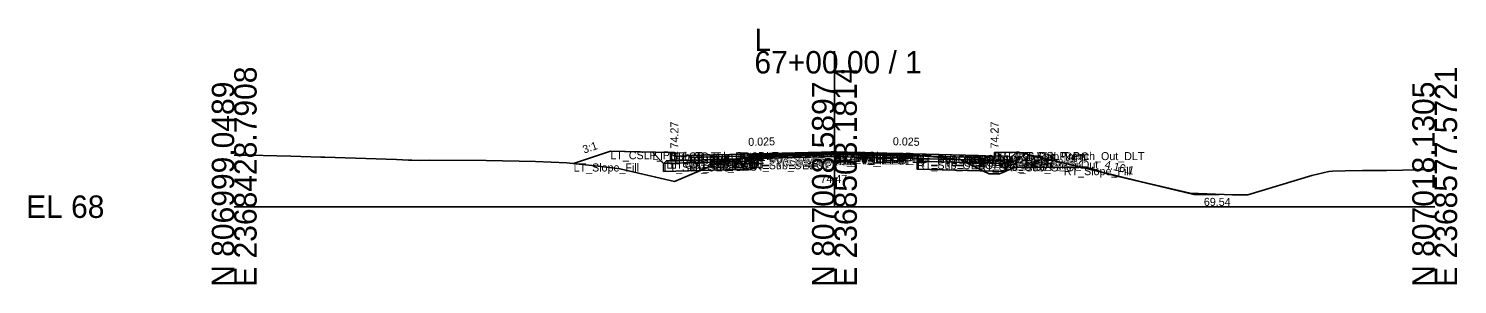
# Model space of a CAD drawing. Extents: x -26 to 8153, y -10 to 9520.
# Drawn here: x 5974.3 to 6152.8, y 7490.3 to 7522.2 of the extents above; entities that cross this region are included whole.
import ezdxf

# ---------------------------------------------------------------- set-up
doc = ezdxf.new("R2010")
doc.units = 0
for name, color, linetype in [('Exist CMT Pavement', 7, 'Continuous'), ('Exist Cross Section Cell', 7, 'Continuous'), ('Exist XS Center Line Elevation Label', 7, 'Continuous'), ('Exist XS Ground Line', 7, 'Continuous'), ('Prop CMT Conc Surface', 7, 'Continuous'), ('Prop CMT Concrete Structures', 7, 'Continuous'), ('Prop CMT Ditch DDE', 7, 'Continuous'), ('Prop CMT Pvmt Course 1', 7, 'Continuous'), ('Prop CMT Pvmt Course 1 CG', 7, 'Continuous'), ('Prop CMT Pvmt Course 1 Wedge', 7, 'Continuous'), ('Prop CMT Pvmt Course 2', 7, 'Continuous'), ('Prop CMT Pvmt Course 2 Wedge', 7, 'Continuous'), ('Prop CMT Pvmt Course 3', 7, 'Continuous'), ('Prop CMT Pvmt Course 3 Wedge', 7, 'Continuous'), ('Prop CMT Pvmt Surface', 7, 'Continuous'), ('Prop CMT Pvmt Wedge Surface 1', 7, 'Continuous'), ('Prop CMT Pvmt Wedge Surface 2', 7, 'Continuous'), ('Prop CMT Pvmt Wedge Surface 3', 7, 'Continuous'), ('Prop CMT Shallow Undercut', 7, 'Continuous'), ('Prop CMT Shallow Undercut Boundary', 7, 'Continuous'), ('Prop CMT Slope Grass', 7, 'Continuous'), ('Prop CMT Subgrade Earthwork', 7, 'Continuous'), ('Prop XS Earthwork Shape', 7, 'Continuous'), ('Prop XS Hydro Elevations', 7, 'Continuous'), ('Prop XS SE Text', 7, 'Continuous'), ('Prop XS Side Slope Text', 7, 'Continuous'), ('Prop XS Subgrade Earthwork', 7, 'Continuous'), ('Scratch_Level_2', 7, 'Continuous'), ('Scratch_Level_6', 7, 'Continuous')]:
    doc.layers.add(name, color=color, linetype=linetype)

msp = doc.modelspace()

# ---------------------------------------------------------------- linework, layer by layer
at = {"layer": 'Exist CMT Pavement'}
for p, q in [((6064.49, 7506.17), (6070.63, 7506.34)), ((6070.63, 7506.34), (6074.8, 7506.47)), ((6074.8, 7506.47), (6077.93, 7506.44)), ((6077.93, 7506.44), (6085.34, 7506.38))]:
    msp.add_line(p, q, dxfattribs=at)
at = {"layer": 'Exist Cross Section Cell'}
for p, q in [((6075, 7500), (6075, 7519.42)), ((6000, 7500), (6075, 7500)), ((6075, 7500), (6150, 7500))]:
    msp.add_line(p, q, dxfattribs=at)
at = {"layer": 'Exist XS Ground Line'}
for p, q in [((6000, 7506.43), (6001.22, 7506.44)), ((6001.22, 7506.44), (6001.89, 7506.42)), ((6001.89, 7506.42), (6007.08, 7506.29)), ((6007.08, 7506.29), (6010.83, 7506.19)), ((6010.83, 7506.19), (6011.31, 7506.19)), ((6011.31, 7506.19), (6020.29, 7505.89)), ((6020.29, 7505.89), (6021.77, 7505.81)), ((6021.77, 7505.81), (6022.18, 7505.82)), ((6022.18, 7505.82), (6023.18, 7505.78)), ((6023.18, 7505.78), (6024.41, 7505.8)), ((6024.41, 7505.8), (6031.47, 7505.77)), ((6031.47, 7505.77), (6037.63, 7505.63)), ((6037.63, 7505.63), (6041.55, 7505.49)), ((6055.82, 7503.47), (6060.95, 7505.68)), ((6060.95, 7505.68), (6061.46, 7505.74)), ((6061.46, 7505.74), (6064.49, 7506.17)), ((6064.49, 7506.17), (6070.63, 7506.34)), ((6070.63, 7506.34), (6074.8, 7506.47)), ((6074.8, 7506.47), (6077.93, 7506.44)), ((6077.93, 7506.44), (6085.34, 7506.38)), ((6085.34, 7506.38), (6087.86, 7506.19)), ((6087.86, 7506.19), (6090.7, 7505.87)), ((6090.7, 7505.87), (6091.42, 7505.51)), ((6041.55, 7505.49), (6045.87, 7505.01)), ((6045.87, 7505.01), (6048.2, 7504.74)), ((6048.2, 7504.74), (6052.68, 7503.68)), ((6091.42, 7505.51), (6094.34, 7504.09)), ((6094.34, 7504.09), (6095.62, 7504.08)), ((6095.62, 7504.08), (6096.88, 7504.63)), ((6096.88, 7504.63), (6097.59, 7504.89)), ((6097.59, 7504.89), (6105.43, 7504.94)), ((6105.43, 7504.94), (6106.45, 7504.92)), ((6106.45, 7504.92), (6109.06, 7504.08)), ((6109.06, 7504.08), (6119.45, 7501.7)), ((6126.65, 7501.49), (6134.66, 7503.9)), ((6134.66, 7503.9), (6136.77, 7504.41)), ((6136.77, 7504.41), (6137.21, 7504.45)), ((6137.21, 7504.45), (6138.8, 7504.49)), ((6138.8, 7504.49), (6141, 7504.51)), ((6141, 7504.51), (6142.46, 7504.5)), ((6142.46, 7504.5), (6143.98, 7504.52)), ((6143.98, 7504.52), (6150, 7504.65)), ((6052.68, 7503.68), (6055.03, 7503.14)), ((6055.03, 7503.14), (6055.82, 7503.47)), ((6119.45, 7501.7), (6124.72, 7501.47)), ((6124.72, 7501.47), (6126.65, 7501.49))]:
    msp.add_line(p, q, dxfattribs=at)
at = {"layer": 'Prop CMT Conc Surface'}
for points in [[(6055, 7506.27), (6055, 7506.77), (6054.5, 7506.77)], [(6057, 7506.4), (6055, 7506.27)], [(6093, 7506.4), (6095, 7506.27)], [(6095, 7506.27), (6095, 7506.77), (6095.5, 7506.77)]]:
    msp.add_lwpolyline(points, dxfattribs=at)
at = {"layer": 'Prop CMT Concrete Structures'}
for points in [[(6057, 7506.4), (6055, 7506.27), (6055, 7506.77), (6054.5, 7506.77)], [(6054.5, 7506.77), (6054.5, 7505.75), (6057, 7505.81)], [(6057, 7505.81), (6057, 7506.4)], [(6093, 7506.4), (6095, 7506.27), (6095, 7506.77), (6095.5, 7506.77)], [(6095.5, 7506.77), (6095.5, 7505.75), (6093, 7505.81)], [(6093, 7505.81), (6093, 7506.4)]]:
    msp.add_lwpolyline(points, dxfattribs=at)
at = {"layer": 'Prop CMT Ditch DDE'}
msp.add_line((6119.92, 7501.54), (6123.05, 7501.54), dxfattribs=at)
msp.add_lwpolyline([(6115.58, 7502.58), (6119.92, 7501.54)], dxfattribs=at)
at = {"layer": 'Prop CMT Pvmt Course 1'}
for points in [[(6075, 7506.85), (6057, 7506.4)], [(6057, 7506.4), (6057, 7506.15)], [(6057, 7506.15), (6064.49, 7506.34)], [(6064.49, 7506.46), (6075, 7506.72)], [(6064.49, 7506.34), (6064.49, 7506.46)], [(6075, 7506.6), (6075, 7506.85)], [(6075, 7506.85), (6093, 7506.4)], [(6075, 7506.6), (6075, 7506.85)], [(6075, 7506.72), (6075, 7506.6), (6075, 7506.6)], [(6085.34, 7506.46), (6075, 7506.72)], [(6075, 7506.72), (6075, 7506.6), (6075, 7506.6)], [(6085.34, 7506.34), (6085.34, 7506.46)], [(6093, 7506.15), (6085.34, 7506.34)], [(6093, 7506.4), (6093, 7506.15)]]:
    msp.add_lwpolyline(points, dxfattribs=at)
at = {"layer": 'Prop CMT Pvmt Course 1 CG'}
for points in [[(6057, 7505.81), (6054, 7505.74), (6053.66, 7505.4)], [(6057, 7505.49), (6057, 7505.81)], [(6093, 7505.81), (6096, 7505.74), (6096.34, 7505.4)], [(6093, 7505.49), (6093, 7505.81)], [(6053.66, 7505.4), (6057, 7505.49)], [(6096.34, 7505.4), (6093, 7505.49)]]:
    msp.add_lwpolyline(points, dxfattribs=at)
at = {"layer": 'Prop CMT Pvmt Course 1 Wedge'}
for points in [[(6075, 7506.72), (6064.49, 7506.46)], [(6075, 7506.72), (6085.34, 7506.46)]]:
    msp.add_lwpolyline(points, dxfattribs=at)
at = {"layer": 'Prop CMT Pvmt Course 2'}
for points in [[(6064.49, 7506.34), (6057, 7506.15)], [(6057, 7506.15), (6057, 7505.82)], [(6057, 7505.82), (6064.49, 7506.01)], [(6064.49, 7506.01), (6064.49, 7506.34)], [(6085.34, 7506.01), (6085.34, 7506.34)], [(6085.34, 7506.34), (6093, 7506.15)], [(6093, 7505.82), (6085.34, 7506.01)], [(6093, 7506.15), (6093, 7505.82)]]:
    msp.add_lwpolyline(points, dxfattribs=at)
at = {"layer": 'Prop CMT Pvmt Course 2 Wedge'}
for points in [[(6075, 7506.6), (6064.49, 7506.34)], [(6075, 7506.6), (6085.34, 7506.34)]]:
    msp.add_lwpolyline(points, dxfattribs=at)
at = {"layer": 'Prop CMT Pvmt Course 3'}
for points in [[(6064.49, 7506.01), (6057, 7505.82)], [(6057, 7505.82), (6057, 7505.49)], [(6057, 7505.49), (6064.49, 7505.67)], [(6064.49, 7505.67), (6064.49, 7506.01)], [(6085.34, 7506.01), (6093, 7505.82)], [(6085.34, 7505.68), (6085.34, 7506.01)], [(6093, 7505.49), (6085.34, 7505.68)], [(6093, 7505.82), (6093, 7505.49)]]:
    msp.add_lwpolyline(points, dxfattribs=at)
at = {"layer": 'Prop CMT Pvmt Course 3 Wedge'}
for points in [[(6075, 7506.27), (6064.49, 7506.01)], [(6075, 7506.27), (6085.34, 7506.01)]]:
    msp.add_lwpolyline(points, dxfattribs=at)
at = {"layer": 'Prop CMT Pvmt Surface'}
for points in [[(6075, 7506.85), (6057, 7506.4)], [(6075, 7506.85), (6093, 7506.4)]]:
    msp.add_lwpolyline(points, dxfattribs=at)
at = {"layer": 'Prop CMT Pvmt Wedge Surface 1'}
for points in [[(6057, 7506.15), (6057, 7506.4)], [(6064.49, 7506.34), (6057, 7506.15)], [(6075, 7506.72), (6064.49, 7506.46)], [(6064.49, 7506.46), (6064.49, 7506.34)], [(6075, 7506.72), (6085.34, 7506.46)], [(6085.34, 7506.46), (6085.34, 7506.34)], [(6085.34, 7506.34), (6093, 7506.15)], [(6093, 7506.15), (6093, 7506.4)]]:
    msp.add_lwpolyline(points, dxfattribs=at)
at = {"layer": 'Prop CMT Pvmt Wedge Surface 2'}
for points in [[(6075, 7506.6), (6057, 7506.15)], [(6057, 7506.15), (6057, 7506.4)], [(6075, 7506.6), (6093, 7506.15)], [(6093, 7506.15), (6093, 7506.4)]]:
    msp.add_lwpolyline(points, dxfattribs=at)
at = {"layer": 'Prop CMT Pvmt Wedge Surface 3'}
for points in [[(6057, 7505.82), (6057, 7506.4)], [(6075, 7506.27), (6057, 7505.82)], [(6075, 7506.27), (6093, 7505.82)], [(6093, 7505.82), (6093, 7506.4)]]:
    msp.add_lwpolyline(points, dxfattribs=at)
at = {"layer": 'Prop CMT Shallow Undercut'}
for points in [[(6060.71, 7505.58), (6064.49, 7505.67), (6064.49, 7504.67), (6058.25, 7504.52)], [(6085.34, 7505.68), (6085.34, 7504.68), (6093.55, 7504.47), (6091.42, 7505.51), (6091.38, 7505.53)]]:
    msp.add_lwpolyline(points, close=True, dxfattribs=at)
at = {"layer": 'Prop CMT Shallow Undercut Boundary'}
for p, q in [((6064.49, 7505.67), (6064.49, 7504.67)), ((6085.34, 7505.68), (6085.34, 7504.68)), ((6053.66, 7505.4), (6053.66, 7504.4)), ((6053.66, 7504.4), (6064.49, 7504.67)), ((6085.34, 7504.68), (6096.34, 7504.4)), ((6096.34, 7505.4), (6096.34, 7504.4))]:
    msp.add_line(p, q, dxfattribs=at)
at = {"layer": 'Prop CMT Slope Grass'}
for points in [[(6054.5, 7506.77), (6047, 7506.92), (6042.41, 7505.39)], [(6095.5, 7506.77), (6098, 7506.82), (6115.58, 7502.58)]]:
    msp.add_lwpolyline(points, dxfattribs=at)
at = {"layer": 'Prop CMT Subgrade Earthwork'}
for points in [[(6057, 7505.49), (6053.66, 7505.4), (6052.25, 7506.81)], [(6064.49, 7505.67), (6057, 7505.49)], [(6064.49, 7505.67), (6064.5, 7506.17)], [(6085.34, 7505.68), (6085.32, 7506.38)], [(6085.34, 7505.68), (6093, 7505.49)], [(6093, 7505.49), (6096.34, 7505.4), (6097.75, 7506.81)]]:
    msp.add_lwpolyline(points, dxfattribs=at)
at = {"layer": 'Prop XS Earthwork Shape'}
for p, q in [((6119.45, 7501.7), (6115.58, 7502.58)), ((6115.58, 7502.58), (6119.92, 7501.54)), ((6123.05, 7501.54), (6119.45, 7501.7)), ((6119.92, 7501.54), (6123.05, 7501.54))]:
    msp.add_line(p, q, dxfattribs=at)
for points in [[(6047, 7506.92), (6042.41, 7505.39), (6045.87, 7505.01), (6048.2, 7504.74), (6052.68, 7503.68), (6055.03, 7503.14), (6055.82, 7503.47), (6058.25, 7504.52), (6053.66, 7504.4), (6053.66, 7505.4), (6052.25, 7506.81)], [(6060.71, 7505.58), (6057, 7505.49), (6053.66, 7505.4), (6053.66, 7504.4), (6058.25, 7504.52)], [(6064.49, 7505.67), (6064.49, 7504.67), (6058.25, 7504.52), (6060.71, 7505.58)], [(6064.49, 7506.17), (6064.5, 7506.17), (6064.49, 7505.67), (6060.71, 7505.58), (6060.95, 7505.68), (6061.46, 7505.74)], [(6085.34, 7505.68), (6085.32, 7506.38), (6085.34, 7506.38), (6087.86, 7506.19), (6090.7, 7505.87), (6091.38, 7505.53)], [(6085.34, 7505.68), (6091.38, 7505.53), (6091.42, 7505.51), (6093.55, 7504.47), (6085.34, 7504.68)], [(6093, 7505.49), (6096.34, 7505.4), (6096.34, 7504.4), (6093.55, 7504.47), (6091.42, 7505.51), (6091.38, 7505.53)], [(6096.34, 7505.4), (6097.75, 7506.81), (6098, 7506.82), (6105.83, 7504.93), (6105.43, 7504.94), (6097.59, 7504.89), (6096.88, 7504.63), (6096.34, 7504.4)], [(6093.55, 7504.47), (6094.34, 7504.09), (6095.62, 7504.08), (6096.34, 7504.4)], [(6105.83, 7504.93), (6106.45, 7504.92), (6108.1, 7504.39)], [(6108.1, 7504.39), (6115.58, 7502.58), (6109.06, 7504.08)]]:
    msp.add_lwpolyline(points, close=True, dxfattribs=at)
at = {"layer": 'Prop XS Subgrade Earthwork'}
for p, q in [((6053.66, 7505.4), (6064.49, 7505.67)), ((6085.34, 7505.68), (6096.34, 7505.4))]:
    msp.add_line(p, q, dxfattribs=at)
at = {"layer": 'Scratch_Level_6'}
for points in [[(6060.71, 7505.58), (6064.49, 7505.67), (6064.49, 7504.67), (6058.25, 7504.52)], [(6085.34, 7505.68), (6085.34, 7504.68), (6093.55, 7504.47), (6091.42, 7505.51), (6091.38, 7505.53)]]:
    msp.add_lwpolyline(points, close=True, dxfattribs=at)

# ---------------------------------------------------------------- texts
at = {"layer": 'Exist Cross Section Cell'}
for s, p in [('L', (6065, 7519.42)), ('67+00.00 / 1', (6065, 7516.62)), ('EL 68', (5974, 7498.6))]:
    msp.add_text(s, height=2.8, dxfattribs=at).set_placement(p)
for s, p in [('E 2368428.7908', (6002.8, 7490)), ('E 2368503.1814', (6077.8, 7490)), ('E 2368577.5721', (6152.8, 7490)), ('N 806999.0489', (6000, 7490)), ('N 807008.5897', (6075, 7490)), ('N 807018.1305', (6150, 7490))]:
    msp.add_text(s, height=2.8, rotation=90, dxfattribs=at).set_placement(p)
at = {"layer": 'Exist XS Center Line Elevation Label'}
msp.add_text('74.47', height=1, dxfattribs=at).set_placement((6073.25, 7502.97))
at = {"layer": 'Prop XS Hydro Elevations'}
for p in [(6055.5, 7507.27), (6095.5, 7507.27)]:
    msp.add_text('74.27', height=1, rotation=90, dxfattribs=at).set_placement(p)
at = {"layer": 'Prop XS SE Text'}
for rotation, p in [(1.4321, (6064.24, 7507.58)), (358.5679, (6082.29, 7507.67))]:
    msp.add_text('0.025', height=1, rotation=rotation, dxfattribs=at).set_placement(p)
at = {"layer": 'Prop XS Side Slope Text'}
for s, rotation, p in [('3:1', 18.4349, (6043.72, 7506.62)), ('4.16:1', 346.9179, (6108.7, 7504.83))]:
    msp.add_text(s, height=1, rotation=rotation, dxfattribs=at).set_placement(p)
msp.add_text('69.54', height=1, dxfattribs=at).set_placement((6121.16, 7500.1))
at = {"layer": 'Scratch_Level_2'}
for s, p in [('LT_CSLP_Pnt', (6047, 7505.92)), ('LT_Sub_Trench_Out_DLT', (6052.25, 7505.81)), ('LT_CG1_Shelf_Out', (6054, 7504.74)), ('LT_CG_Top_BOC', (6054.5, 7505.77)), ('LT_CG_Bot_BOC', (6054.5, 7504.75)), ('LT_CG_Top_Face', (6055, 7505.77)), ('LT_CG_Top_Gut', (6055, 7505.27)), ('LT_PV1_OEOT', (6057, 7505.4)), ('LT_PV2_OEOT', (6057, 7505.15)), ('LT_PV3_OEOT', (6057, 7504.82)), ('LT_CG_Bot_IE', (6057, 7504.81)), ('LT_Sub_OEOT', (6057, 7504.49)), ('LT_PV1_OEEOP', (6064.49, 7505.46)), ('LT_PV2_OEEOP', (6064.49, 7505.34)), ('LT_PV_OEEOP_EG', (6064.49, 7505.17)), ('LT_PV3_OEEOP', (6064.49, 7505.01)), ('LT_Sub_OEEOP', (6064.49, 7504.67)), ('LT_PV_Sub_Tie_Out', (6064.5, 7505.17)), ('PV1_PGL', (6075, 7505.85)), ('RT_PV1_IEEOP', (6075, 7505.72)), ('LT_PV1_IEEOP', (6075, 7505.72)), ('RT_PV2_IEEOP', (6075, 7505.6)), ('LT_PV2_IEEOP', (6075, 7505.6)), ('PV2_PGL', (6075, 7505.6)), ('RT_PV_IEEOP_EG', (6075, 7505.47)), ('LT_PV_IEEOP_EG', (6075, 7505.47)), ('RT_PV3_IEEOP', (6075, 7505.27)), ('LT_PV3_IEEOP', (6075, 7505.27)), ('RT_PV_Sub_Tie_Out', (6085.32, 7505.38)), ('RT_PV1_OEEOP', (6085.34, 7505.46)), ('RT_PV_OEEOP_EG', (6085.34, 7505.38)), ('RT_PV2_OEEOP', (6085.34, 7505.34)), ('RT_PV3_OEEOP', (6085.34, 7505.01)), ('RT_Sub_OEEOP', (6085.34, 7504.68)), ('RT_PV1_OEOT', (6093, 7505.4)), ('RT_PV2_OEOT', (6093, 7505.15)), ('RT_PV3_OEOT', (6093, 7504.82)), ('RT_CG_Bot_IE', (6093, 7504.81)), ('RT_Sub_OEOT', (6093, 7504.49)), ('RT_CG_Top_Face', (6095, 7505.77)), ('RT_CG_Top_Gut', (6095, 7505.27)), ('RT_CG_Top_BOC', (6095.5, 7505.77)), ('RT_CG_Bot_BOC', (6095.5, 7504.75)), ('RT_CG1_Shelf_Out', (6096, 7504.74)), ('RT_Sub_Trench_Out_DLT', (6097.75, 7505.81)), ('RT_CSLP_Pnt', (6098, 7505.82)), ('LT_Slope_Fill', (6042.41, 7504.39)), ('LT_Sub_OEOP', (6053.66, 7504.4)), ('RT_Sub_OEOP', (6096.34, 7504.4)), ('RT_Slope_Fill', (6103.66, 7503.93))]:
    msp.add_text(s, height=1, dxfattribs=at).set_placement(p)

doc.saveas('drawing.dxf')
